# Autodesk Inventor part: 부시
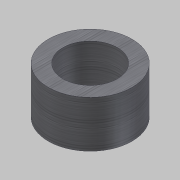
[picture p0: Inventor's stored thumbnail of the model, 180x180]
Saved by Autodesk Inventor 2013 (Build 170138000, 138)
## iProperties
Company: 한국ATC센터
Created: 2014-10
Part Number: 부시
Document SubType Name: Modeling
Designer: 한국ATC센터
Density: 7.86 g/cm^3
Material: 강, 연강
Mass: 157.788 g
Surface Area: 70.2617 cm^2
Volume: 20.0748 cm^3
Author: KYOUNG IL JANG
Revision Number: 1
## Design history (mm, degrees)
sketch "스케치1"
  geometry: C1 r 21.5 at (0, 0) reference; C2 r 31 at (0, 0) reference; C3 r 14 at (0, 0) reference; 1 further point
  node "참조1"
  node "참조2"
node "작업 평면1"
extrude "돌출1" new body sketch "스케치1" stored distance "d0" = 10; taper "d1" = 0 deg
node "솔리드1"
